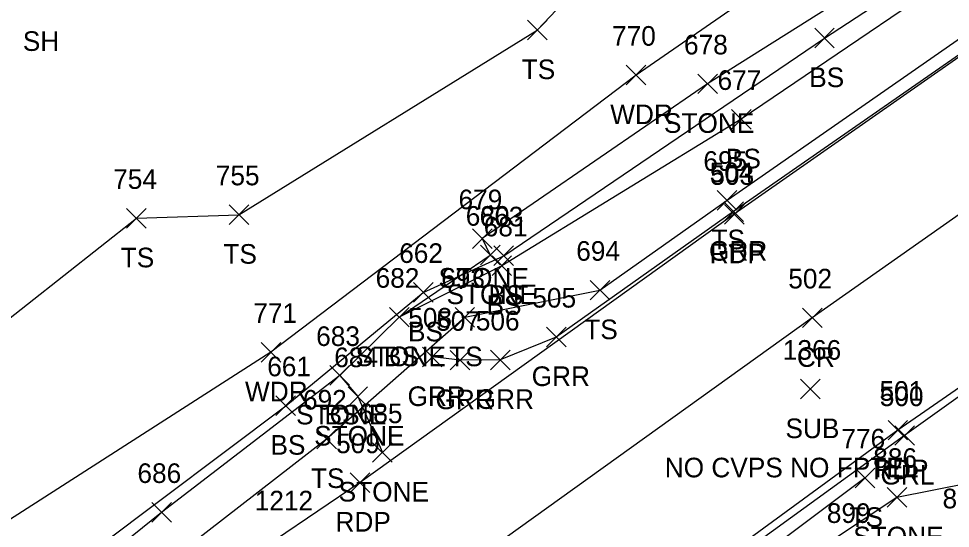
# Model space of a CAD drawing. Extents: x 1528286 to 1556263, y 492387 to 508952.
# Drawn here: x 1528541.2 to 1528636.2, y 492742 to 492794 of the extents above; entities that cross this region are included whole.
import ezdxf

# ---------------------------------------------------------------- set-up
doc = ezdxf.new("R2010")
doc.units = 0
for name, color, linetype in [('L_A', 7, 'Continuous'), ('L_I', 7, 'Continuous'), ('L_TIC', 7, 'Continuous'), ('LASF', 7, 'Continuous'), ('LAWA', 7, 'Continuous'), ('LELB', 7, 'Continuous'), ('P_A', 7, 'Continuous'), ('P_I', 7, 'Continuous'), ('P_TIC', 7, 'Continuous'), ('PET', 7, 'Continuous'), ('PRC', 7, 'Continuous'), ('R_A', 7, 'Continuous'), ('R_I', 7, 'Continuous'), ('R_TIC', 7, 'Continuous'), ('RGR', 7, 'Continuous'), ('U_A', 7, 'Continuous'), ('U_C', 7, 'Continuous'), ('U_I', 7, 'Continuous'), ('U_TIC', 7, 'Continuous')]:
    doc.layers.add(name, color=color, linetype=linetype)

msp = doc.modelspace()

# ---------------------------------------------------------------- linework, layer by layer
at = {"layer": 'L_TIC'}
for points in [[(1528593.12, 492791.873), (1528595.12, 492793.873)], [(1528595.12, 492791.873), (1528593.12, 492793.873)], [(1528593.12, 492791.873), (1528595.12, 492793.873)], [(1528595.12, 492791.873), (1528593.12, 492793.873)], [(1528622.394, 492791.056), (1528624.394, 492793.056)], [(1528624.394, 492791.056), (1528622.394, 492793.056)], [(1528622.394, 492791.056), (1528624.394, 492793.056)], [(1528624.394, 492791.056), (1528622.394, 492793.056)], [(1528603.188, 492787.279), (1528605.188, 492789.279)], [(1528605.188, 492787.279), (1528603.188, 492789.279)], [(1528603.188, 492787.279), (1528605.188, 492789.279)], [(1528605.188, 492787.279), (1528603.188, 492789.279)], [(1528610.484, 492786.39), (1528612.484, 492788.39)], [(1528612.484, 492786.39), (1528610.484, 492788.39)], [(1528610.484, 492786.39), (1528612.484, 492788.39)], [(1528612.484, 492786.39), (1528610.484, 492788.39)], [(1528613.904, 492782.769), (1528615.904, 492784.769)], [(1528615.904, 492782.769), (1528613.904, 492784.769)], [(1528613.904, 492782.769), (1528615.904, 492784.769)], [(1528615.904, 492782.769), (1528613.904, 492784.769)], [(1528612.458, 492774.516), (1528614.458, 492776.516)], [(1528614.458, 492774.516), (1528612.458, 492776.516)], [(1528612.458, 492774.516), (1528614.458, 492776.516)], [(1528614.458, 492774.516), (1528612.458, 492776.516)], [(1528562.708, 492773.042), (1528564.708, 492775.042)], [(1528564.708, 492773.042), (1528562.708, 492775.042)], [(1528562.708, 492773.042), (1528564.708, 492775.042)], [(1528564.708, 492773.042), (1528562.708, 492775.042)], [(1528552.244, 492772.675), (1528554.244, 492774.675)], [(1528554.244, 492772.675), (1528552.244, 492774.675)], [(1528552.244, 492772.675), (1528554.244, 492774.675)], [(1528554.244, 492772.675), (1528552.244, 492774.675)], [(1528587.506, 492770.6), (1528589.506, 492772.6)], [(1528589.506, 492770.6), (1528587.506, 492772.6)], [(1528587.506, 492770.6), (1528589.506, 492772.6)], [(1528589.506, 492770.6), (1528587.506, 492772.6)], [(1528588.322, 492768.92), (1528590.322, 492770.92)], [(1528590.322, 492768.92), (1528588.322, 492770.92)], [(1528588.322, 492768.92), (1528590.322, 492770.92)], [(1528590.322, 492768.92), (1528588.322, 492770.92)], [(1528589.696, 492768.852), (1528591.696, 492770.852)], [(1528591.696, 492768.852), (1528589.696, 492770.852)], [(1528589.696, 492768.852), (1528591.696, 492770.852)], [(1528591.696, 492768.852), (1528589.696, 492770.852)], [(1528589.503, 492767.834), (1528591.503, 492769.834)], [(1528591.503, 492767.834), (1528589.503, 492769.834)], [(1528589.503, 492767.834), (1528591.503, 492769.834)], [(1528591.503, 492767.834), (1528589.503, 492769.834)], [(1528581.496, 492765.122), (1528583.496, 492767.122)], [(1528583.496, 492765.122), (1528581.496, 492767.122)], [(1528581.496, 492765.122), (1528583.496, 492767.122)], [(1528583.496, 492765.122), (1528581.496, 492767.122)], [(1528599.497, 492765.346), (1528601.497, 492767.346)], [(1528601.497, 492765.346), (1528599.497, 492767.346)], [(1528599.497, 492765.346), (1528601.497, 492767.346)], [(1528601.497, 492765.346), (1528599.497, 492767.346)], [(1528579.049, 492762.591), (1528581.049, 492764.591)], [(1528581.049, 492762.591), (1528579.049, 492764.591)], [(1528579.049, 492762.591), (1528581.049, 492764.591)], [(1528581.049, 492762.591), (1528579.049, 492764.591)], [(1528579.049, 492762.591), (1528581.049, 492764.591)], [(1528581.049, 492762.591), (1528579.049, 492764.591)], [(1528579.049, 492762.591), (1528581.049, 492764.591)], [(1528581.049, 492762.591), (1528579.049, 492764.591)], [(1528585.729, 492762.586), (1528587.729, 492764.586)], [(1528587.729, 492762.586), (1528585.729, 492764.586)], [(1528585.729, 492762.586), (1528587.729, 492764.586)], [(1528587.729, 492762.586), (1528585.729, 492764.586)], [(1528565.961, 492759.007), (1528567.961, 492761.007)], [(1528567.961, 492759.007), (1528565.961, 492761.007)], [(1528565.961, 492759.007), (1528567.961, 492761.007)], [(1528567.961, 492759.007), (1528565.961, 492761.007)], [(1528572.986, 492756.651), (1528574.986, 492758.651)], [(1528574.986, 492756.651), (1528572.986, 492758.651)], [(1528572.986, 492756.651), (1528574.986, 492758.651)], [(1528574.986, 492756.651), (1528572.986, 492758.651)], [(1528572.986, 492756.651), (1528574.986, 492758.651)], [(1528574.986, 492756.651), (1528572.986, 492758.651)], [(1528572.986, 492756.651), (1528574.986, 492758.651)], [(1528574.986, 492756.651), (1528572.986, 492758.651)], [(1528574.825, 492754.492), (1528576.825, 492756.492)], [(1528576.825, 492754.492), (1528574.825, 492756.492)], [(1528574.825, 492754.492), (1528576.825, 492756.492)], [(1528576.825, 492754.492), (1528574.825, 492756.492)], [(1528567.475, 492753.562), (1528569.475, 492755.562)], [(1528569.475, 492753.562), (1528567.475, 492755.562)], [(1528567.475, 492753.562), (1528569.475, 492755.562)], [(1528569.475, 492753.562), (1528567.475, 492755.562)], [(1528571.642, 492750.164), (1528573.642, 492752.164)], [(1528573.642, 492750.164), (1528571.642, 492752.164)], [(1528571.642, 492750.164), (1528573.642, 492752.164)], [(1528573.642, 492750.164), (1528571.642, 492752.164)], [(1528577.324, 492748.784), (1528579.324, 492750.784)], [(1528579.324, 492748.784), (1528577.324, 492750.784)], [(1528577.324, 492748.784), (1528579.324, 492750.784)], [(1528579.324, 492748.784), (1528577.324, 492750.784)], [(1528626.535, 492746.197), (1528628.535, 492748.197)], [(1528628.535, 492746.197), (1528626.535, 492748.197)], [(1528626.535, 492746.197), (1528628.535, 492748.197)], [(1528628.535, 492746.197), (1528626.535, 492748.197)], [(1528629.781, 492744.216), (1528631.781, 492746.216)], [(1528631.781, 492744.216), (1528629.781, 492746.216)], [(1528629.781, 492744.216), (1528631.781, 492746.216)], [(1528631.781, 492744.216), (1528629.781, 492746.216)], [(1528554.822, 492742.679), (1528556.822, 492744.679)], [(1528556.822, 492742.679), (1528554.822, 492744.679)], [(1528554.822, 492742.679), (1528556.822, 492744.679)], [(1528556.822, 492742.679), (1528554.822, 492744.679)]]:
    msp.add_lwpolyline(points, dxfattribs=at)
at = {"layer": 'LASF'}
for points in [[(1528676.156, 492847.515), (1528666.204, 492828.052), (1528662.64, 492823.68), (1528640.743, 492805.862), (1528611.484, 492787.39), (1528588.506, 492771.6), (1528589.322, 492769.92)], [(1528676.156, 492847.515), (1528666.204, 492828.052), (1528662.64, 492823.68), (1528640.743, 492805.862), (1528611.484, 492787.39), (1528588.506, 492771.6), (1528589.322, 492769.92)], [(1528580.049, 492763.591), (1528589.322, 492769.92)], [(1528580.049, 492763.591), (1528589.322, 492769.92)], [(1528580.049, 492763.591), (1528573.986, 492757.651), (1528575.825, 492755.492), (1528578.324, 492749.784)], [(1528580.049, 492763.591), (1528573.986, 492757.651), (1528575.825, 492755.492), (1528578.324, 492749.784)], [(1528639.098, 492735.608), (1528627.241, 492716.245), (1528613.209, 492719.227), (1528607.642, 492721.098), (1528613.116, 492733.507), (1528630.781, 492745.216), (1528656.998, 492750.434), (1528671.474, 492742.478), (1528668.765, 492730.184), (1528658.721, 492713.827), (1528653.721, 492719.292), (1528645.341, 492731.093)], [(1528639.098, 492735.608), (1528627.241, 492716.245), (1528613.209, 492719.227), (1528607.642, 492721.098), (1528613.116, 492733.507), (1528630.781, 492745.216), (1528656.998, 492750.434), (1528671.474, 492742.478), (1528668.765, 492730.184), (1528658.721, 492713.827), (1528653.721, 492719.292), (1528645.341, 492731.093)]]:
    msp.add_lwpolyline(points, dxfattribs=at)
at = {"layer": 'LAWA'}
msp.add_lwpolyline([(1528662.937, 492830.692), (1528634.182, 492809.012), (1528604.188, 492788.279), (1528566.961, 492760.007), (1528530.313, 492736.522), (1528502.638, 492712.533), (1528486.776, 492718.401), (1528471.218, 492734.886)], dxfattribs=at)
msp.add_lwpolyline([(1528662.937, 492830.692), (1528634.182, 492809.012), (1528604.188, 492788.279), (1528566.961, 492760.007), (1528530.313, 492736.522), (1528502.638, 492712.533), (1528486.776, 492718.401), (1528471.218, 492734.886)], dxfattribs=at)
at = {"layer": 'LELB'}
for points in [[(1528511.531, 492702.846), (1528534.14, 492721.314), (1528572.642, 492751.164), (1528586.729, 492763.586), (1528600.497, 492766.346), (1528613.458, 492775.516), (1528652.2, 492802.526), (1528688.619, 492828.262), (1528710.289, 492843.118), (1528742.907, 492866.471), (1528778.713, 492891.266), (1528817.445, 492919.082), (1528857.746, 492946.937), (1528897.372, 492973.983), (1528940.286, 493003.739)], [(1528511.531, 492702.846), (1528534.14, 492721.314), (1528572.642, 492751.164), (1528586.729, 492763.586), (1528600.497, 492766.346), (1528613.458, 492775.516), (1528652.2, 492802.526), (1528688.619, 492828.262), (1528710.289, 492843.118), (1528742.907, 492866.471), (1528778.713, 492891.266), (1528817.445, 492919.082), (1528857.746, 492946.937), (1528897.372, 492973.983), (1528940.286, 493003.739)], [(1528479.267, 492740.393), (1528490.259, 492728.467), (1528495.219, 492727.605), (1528516.649, 492745.843), (1528531.015, 492756.158), (1528553.244, 492773.675), (1528563.708, 492774.042), (1528594.12, 492792.873), (1528616.34, 492816.289), (1528631.227, 492827.673), (1528655.587, 492852.622)], [(1528479.267, 492740.393), (1528490.259, 492728.467), (1528495.219, 492727.605), (1528516.649, 492745.843), (1528531.015, 492756.158), (1528553.244, 492773.675), (1528563.708, 492774.042), (1528594.12, 492792.873), (1528616.34, 492816.289), (1528631.227, 492827.673), (1528655.587, 492852.622)], [(1528476.47, 492733.086), (1528490.627, 492720.26), (1528499.344, 492715.307), (1528510.272, 492713.09), (1528516.407, 492713.286), (1528530.473, 492725.995), (1528568.475, 492754.562), (1528582.496, 492766.122), (1528590.696, 492769.852), (1528623.394, 492792.056), (1528660.048, 492816.01), (1528671.542, 492831.179), (1528678.095, 492847.611)], [(1528476.47, 492733.086), (1528490.627, 492720.26), (1528499.344, 492715.307), (1528510.272, 492713.09), (1528516.407, 492713.286), (1528530.473, 492725.995), (1528568.475, 492754.562), (1528582.496, 492766.122), (1528590.696, 492769.852), (1528623.394, 492792.056), (1528660.048, 492816.01), (1528671.542, 492831.179), (1528678.095, 492847.611)], [(1528685.936, 492838.575), (1528672.607, 492830.811), (1528666.617, 492820.24), (1528643.207, 492802.995), (1528614.904, 492783.769), (1528590.503, 492768.834), (1528580.049, 492763.591), (1528573.986, 492757.651), (1528555.822, 492743.679), (1528531.303, 492723.898), (1528516.93, 492710.506), (1528511.372, 492706.597)], [(1528685.936, 492838.575), (1528672.607, 492830.811), (1528666.617, 492820.24), (1528643.207, 492802.995), (1528614.904, 492783.769), (1528590.503, 492768.834), (1528580.049, 492763.591), (1528573.986, 492757.651), (1528555.822, 492743.679), (1528531.303, 492723.898), (1528516.93, 492710.506), (1528511.372, 492706.597)], [(1528627.535, 492747.197), (1528602.245, 492728.24), (1528590.919, 492720.18), (1528561.7, 492697.236), (1528528.44, 492669.894), (1528504.886, 492649.176), (1528486.55, 492633.133), (1528477.153, 492624.603), (1528462.188, 492611.303), (1528435.473, 492586.893), (1528420.499, 492573.078), (1528389.262, 492542.582), (1528363.671, 492517.292), (1528340.83, 492494.601)], [(1528627.535, 492747.197), (1528602.245, 492728.24), (1528590.919, 492720.18), (1528561.7, 492697.236), (1528528.44, 492669.894), (1528504.886, 492649.176), (1528486.55, 492633.133), (1528477.153, 492624.603), (1528462.188, 492611.303), (1528435.473, 492586.893), (1528420.499, 492573.078), (1528389.262, 492542.582), (1528363.671, 492517.292), (1528340.83, 492494.601)]]:
    msp.add_lwpolyline(points, dxfattribs=at)
at = {"layer": 'P_TIC'}
for points in [[(1528613.2, 492773.085), (1528615.2, 492775.085)], [(1528615.2, 492773.085), (1528613.2, 492775.085)], [(1528613.2, 492773.085), (1528615.2, 492775.085)], [(1528615.2, 492773.085), (1528613.2, 492775.085)], [(1528621.148, 492762.521), (1528623.148, 492764.521)], [(1528623.148, 492762.521), (1528621.148, 492764.521)], [(1528621.148, 492762.521), (1528623.148, 492764.521)], [(1528623.148, 492762.521), (1528621.148, 492764.521)], [(1528629.871, 492751.063), (1528631.871, 492753.063)], [(1528631.871, 492751.063), (1528629.871, 492753.063)], [(1528629.871, 492751.063), (1528631.871, 492753.063)], [(1528631.871, 492751.063), (1528629.871, 492753.063)], [(1528575.056, 492745.716), (1528577.056, 492747.716)], [(1528577.056, 492745.716), (1528575.056, 492747.716)], [(1528575.056, 492745.716), (1528577.056, 492747.716)], [(1528577.056, 492745.716), (1528575.056, 492747.716)]]:
    msp.add_lwpolyline(points, dxfattribs=at)
at = {"layer": 'PET'}
for points in [[(1528653.332, 492801.515), (1528614.2, 492774.085)], [(1528653.332, 492801.515), (1528614.2, 492774.085)], [(1528668.887, 492778.385), (1528630.871, 492752.063)], [(1528668.887, 492778.385), (1528630.871, 492752.063)], [(1528614.2, 492774.085), (1528576.056, 492746.716)], [(1528614.2, 492774.085), (1528576.056, 492746.716)], [(1528630.871, 492752.063), (1528592.558, 492724.002)], [(1528630.871, 492752.063), (1528592.558, 492724.002)], [(1528576.056, 492746.716), (1528567.438, 492740.881)], [(1528576.056, 492746.716), (1528567.438, 492740.881)]]:
    msp.add_lwpolyline(points, dxfattribs=at)
at = {"layer": 'PRC'}
for points in [[(1528660.714, 492790.64), (1528622.148, 492763.521)], [(1528660.714, 492790.64), (1528622.148, 492763.521)], [(1528622.148, 492763.521), (1528583.75, 492735.932)], [(1528622.148, 492763.521), (1528583.75, 492735.932)]]:
    msp.add_lwpolyline(points, dxfattribs=at)
at = {"layer": 'R_TIC'}
for points in [[(1528613.133, 492773.352), (1528615.133, 492775.352)], [(1528615.133, 492773.352), (1528613.133, 492775.352)], [(1528613.133, 492773.352), (1528615.133, 492775.352)], [(1528615.133, 492773.352), (1528613.133, 492775.352)], [(1528595.056, 492760.567), (1528597.056, 492762.567)], [(1528597.056, 492760.567), (1528595.056, 492762.567)], [(1528595.056, 492760.567), (1528597.056, 492762.567)], [(1528597.056, 492760.567), (1528595.056, 492762.567)], [(1528582.403, 492758.529), (1528584.403, 492760.529)], [(1528584.403, 492758.529), (1528582.403, 492760.529)], [(1528582.403, 492758.529), (1528584.403, 492760.529)], [(1528584.403, 492758.529), (1528582.403, 492760.529)], [(1528585.25, 492758.202), (1528587.25, 492760.202)], [(1528587.25, 492758.202), (1528585.25, 492760.202)], [(1528585.25, 492758.202), (1528587.25, 492760.202)], [(1528587.25, 492758.202), (1528585.25, 492760.202)], [(1528589.348, 492758.232), (1528591.348, 492760.232)], [(1528591.348, 492758.232), (1528589.348, 492760.232)], [(1528589.348, 492758.232), (1528591.348, 492760.232)], [(1528591.348, 492758.232), (1528589.348, 492760.232)], [(1528630.557, 492750.518), (1528632.557, 492752.518)], [(1528632.557, 492750.518), (1528630.557, 492752.518)], [(1528630.557, 492750.518), (1528632.557, 492752.518)], [(1528632.557, 492750.518), (1528630.557, 492752.518)]]:
    msp.add_lwpolyline(points, dxfattribs=at)
at = {"layer": 'RGR'}
for points in [[(1528653.301, 492801.623), (1528614.133, 492774.352)], [(1528653.301, 492801.623), (1528614.133, 492774.352)], [(1528666.696, 492776.663), (1528631.557, 492751.518)], [(1528666.696, 492776.663), (1528631.557, 492751.518)], [(1528614.133, 492774.352), (1528596.056, 492761.567), (1528590.348, 492759.232), (1528586.25, 492759.202), (1528583.403, 492759.529)], [(1528614.133, 492774.352), (1528596.056, 492761.567), (1528590.348, 492759.232), (1528586.25, 492759.202), (1528583.403, 492759.529)], [(1528631.557, 492751.518), (1528593.228, 492723.7), (1528555.254, 492694.171), (1528520.288, 492664.562), (1528486.051, 492634.677), (1528450.283, 492602.919), (1528412.918, 492568.153), (1528376.626, 492531.198), (1528339.769, 492495.46)], [(1528631.557, 492751.518), (1528593.228, 492723.7), (1528555.254, 492694.171), (1528520.288, 492664.562), (1528486.051, 492634.677), (1528450.283, 492602.919), (1528412.918, 492568.153), (1528376.626, 492531.198), (1528339.769, 492495.46)]]:
    msp.add_lwpolyline(points, dxfattribs=at)
at = {"layer": 'U_TIC'}
for points in [[(1528620.943, 492755.252), (1528622.943, 492757.252)], [(1528622.943, 492755.252), (1528620.943, 492757.252)], [(1528620.943, 492755.252), (1528622.943, 492757.252)], [(1528622.943, 492755.252), (1528620.943, 492757.252)]]:
    msp.add_lwpolyline(points, dxfattribs=at)

# ---------------------------------------------------------------- texts
at = {"layer": 'L_A'}
for s, p in [('SH', (1528541.671, 492790.748)), ('SH', (1528541.671, 492790.748)), ('TS', (1528592.529, 492787.873)), ('TS', (1528592.529, 492787.873)), ('BS', (1528621.835, 492787.056)), ('BS', (1528621.835, 492787.056)), ('WDR', (1528601.55, 492783.279)), ('WDR', (1528601.55, 492783.279)), ('STONE', (1528607.027, 492782.39)), ('STONE', (1528607.027, 492782.39)), ('BS', (1528613.344, 492778.769)), ('BS', (1528613.344, 492778.769)), ('TS', (1528611.868, 492770.516)), ('TS', (1528611.868, 492770.516)), ('TS', (1528551.653, 492768.675)), ('TS', (1528551.653, 492768.675)), ('TS', (1528562.118, 492769.042)), ('TS', (1528562.118, 492769.042)), ('STONE', (1528584.049, 492766.6)), ('STONE', (1528584.049, 492766.6)), ('STONE', (1528584.866, 492764.92)), ('STONE', (1528584.866, 492764.92)), ('BS', (1528589.137, 492764.852)), ('BS', (1528589.137, 492764.852)), ('BS', (1528588.944, 492763.834)), ('BS', (1528588.944, 492763.834)), ('BS', (1528580.937, 492761.122)), ('BS', (1528580.937, 492761.122)), ('TS', (1528598.907, 492761.346)), ('TS', (1528598.907, 492761.346)), ('STONE', (1528575.592, 492758.591)), ('STONE', (1528575.592, 492758.591)), ('BS', (1528578.49, 492758.591)), ('BS', (1528578.49, 492758.591)), ('TS', (1528585.139, 492758.586)), ('TS', (1528585.139, 492758.586)), ('WDR', (1528564.323, 492755.007)), ('WDR', (1528564.323, 492755.007)), ('STONE', (1528569.529, 492752.651)), ('STONE', (1528569.529, 492752.651)), ('BS', (1528572.427, 492752.651)), ('BS', (1528572.427, 492752.651)), ('STONE', (1528571.369, 492750.492)), ('STONE', (1528571.369, 492750.492)), ('BS', (1528566.916, 492749.562)), ('BS', (1528566.916, 492749.562)), ('TS', (1528571.052, 492746.164)), ('TS', (1528571.052, 492746.164)), ('STONE', (1528573.868, 492744.784)), ('STONE', (1528573.868, 492744.784)), ('TS', (1528625.945, 492742.197)), ('TS', (1528625.945, 492742.197)), ('STONE', (1528626.324, 492740.216)), ('STONE', (1528626.324, 492740.216))]:
    msp.add_text(s, height=2, dxfattribs=at).set_placement(p)
at = {"layer": 'L_I'}
for s, p in [('770', (1528601.739, 492791.279)), ('770', (1528601.739, 492791.279)), ('678', (1528609.074, 492790.39)), ('678', (1528609.074, 492790.39)), ('677', (1528612.494, 492786.769)), ('677', (1528612.494, 492786.769)), ('695', (1528611.049, 492778.516)), ('695', (1528611.049, 492778.516)), ('755', (1528561.346, 492777.042)), ('755', (1528561.346, 492777.042)), ('754', (1528550.882, 492776.675)), ('754', (1528550.882, 492776.675)), ('679', (1528586.089, 492774.6)), ('679', (1528586.089, 492774.6)), ('680', (1528586.826, 492772.92)), ('680', (1528586.826, 492772.92)), ('663', (1528588.239, 492772.852)), ('663', (1528588.239, 492772.852)), ('681', (1528588.661, 492771.834)), ('681', (1528588.661, 492771.834)), ('694', (1528598.088, 492769.346)), ('694', (1528598.088, 492769.346)), ('662', (1528580.039, 492769.122)), ('662', (1528580.039, 492769.122)), ('682', (1528577.639, 492766.591)), ('682', (1528577.639, 492766.591)), ('682', (1528577.639, 492766.591)), ('682', (1528577.639, 492766.591)), ('693', (1528584.32, 492766.586)), ('693', (1528584.32, 492766.586)), ('771', (1528565.166, 492763.007)), ('771', (1528565.166, 492763.007)), ('683', (1528571.577, 492760.651)), ('683', (1528571.577, 492760.651)), ('683', (1528571.577, 492760.651)), ('683', (1528571.577, 492760.651)), ('684', (1528573.416, 492758.492)), ('684', (1528573.416, 492758.492)), ('661', (1528566.585, 492757.562)), ('661', (1528566.585, 492757.562)), ('692', (1528570.233, 492754.164)), ('692', (1528570.233, 492754.164)), ('685', (1528575.915, 492752.784)), ('685', (1528575.915, 492752.784)), ('776', (1528625.118, 492750.197)), ('776', (1528625.118, 492750.197)), ('886', (1528628.363, 492748.216)), ('886', (1528628.363, 492748.216)), ('686', (1528553.357, 492746.679)), ('686', (1528553.357, 492746.679)), ('898', (1528635.428, 492744.092)), ('898', (1528635.428, 492744.092)), ('899', (1528623.635, 492742.602)), ('899', (1528623.635, 492742.602))]:
    msp.add_text(s, height=2, dxfattribs=at).set_placement(p)
at = {"layer": 'P_A'}
for s, p in [('RDP', (1528611.688, 492769.085)), ('RDP', (1528611.688, 492769.085)), ('CR', (1528620.581, 492758.521)), ('CR', (1528620.581, 492758.521)), ('RDP', (1528628.359, 492747.063)), ('RDP', (1528628.359, 492747.063)), ('RDP', (1528573.544, 492741.716)), ('RDP', (1528573.544, 492741.716))]:
    msp.add_text(s, height=2, dxfattribs=at).set_placement(p)
at = {"layer": 'P_I'}
for s, p in [('503', (1528611.759, 492777.085)), ('503', (1528611.759, 492777.085)), ('502', (1528619.707, 492766.521)), ('502', (1528619.707, 492766.521)), ('501', (1528628.997, 492755.063)), ('501', (1528628.997, 492755.063)), ('509', (1528573.607, 492749.716)), ('509', (1528573.607, 492749.716)), ('1212', (1528565.312, 492743.881)), ('1212', (1528565.312, 492743.881))]:
    msp.add_text(s, height=2, dxfattribs=at).set_placement(p)
at = {"layer": 'R_A'}
for s, p in [('GRR', (1528611.621, 492769.352)), ('GRR', (1528611.621, 492769.352)), ('GRR', (1528593.544, 492756.567)), ('GRR', (1528593.544, 492756.567)), ('GRR', (1528580.891, 492754.529)), ('GRR', (1528580.891, 492754.529)), ('GRR', (1528583.738, 492754.202)), ('GRR', (1528583.738, 492754.202)), ('GRR', (1528587.836, 492754.232)), ('GRR', (1528587.836, 492754.232)), ('GRL', (1528629.101, 492746.518)), ('GRL', (1528629.101, 492746.518))]:
    msp.add_text(s, height=2, dxfattribs=at).set_placement(p)
at = {"layer": 'R_I'}
for s, p in [('504', (1528611.692, 492777.352)), ('504', (1528611.692, 492777.352)), ('505', (1528593.615, 492764.567)), ('505', (1528593.615, 492764.567)), ('508', (1528580.962, 492762.529)), ('508', (1528580.962, 492762.529)), ('507', (1528583.809, 492762.202)), ('507', (1528583.809, 492762.202)), ('506', (1528587.852, 492762.232)), ('506', (1528587.852, 492762.232)), ('500', (1528629.03, 492754.518)), ('500', (1528629.03, 492754.518))]:
    msp.add_text(s, height=2, dxfattribs=at).set_placement(p)
at = {"layer": 'U_A'}
msp.add_text('SUB', height=2, dxfattribs=at).set_placement((1528619.416, 492751.252))
msp.add_text('SUB', height=2, dxfattribs=at).set_placement((1528619.416, 492751.252))
at = {"layer": 'U_C'}
msp.add_text('NO CVPS NO FPTEL', height=2, dxfattribs=at).set_placement((1528607.108, 492747.252))
msp.add_text('NO CVPS NO FPTEL', height=2, dxfattribs=at).set_placement((1528607.108, 492747.252))
at = {"layer": 'U_I'}
msp.add_text('1366', height=2, dxfattribs=at).set_placement((1528619.148, 492759.252))
msp.add_text('1366', height=2, dxfattribs=at).set_placement((1528619.148, 492759.252))

doc.saveas('drawing.dxf')
